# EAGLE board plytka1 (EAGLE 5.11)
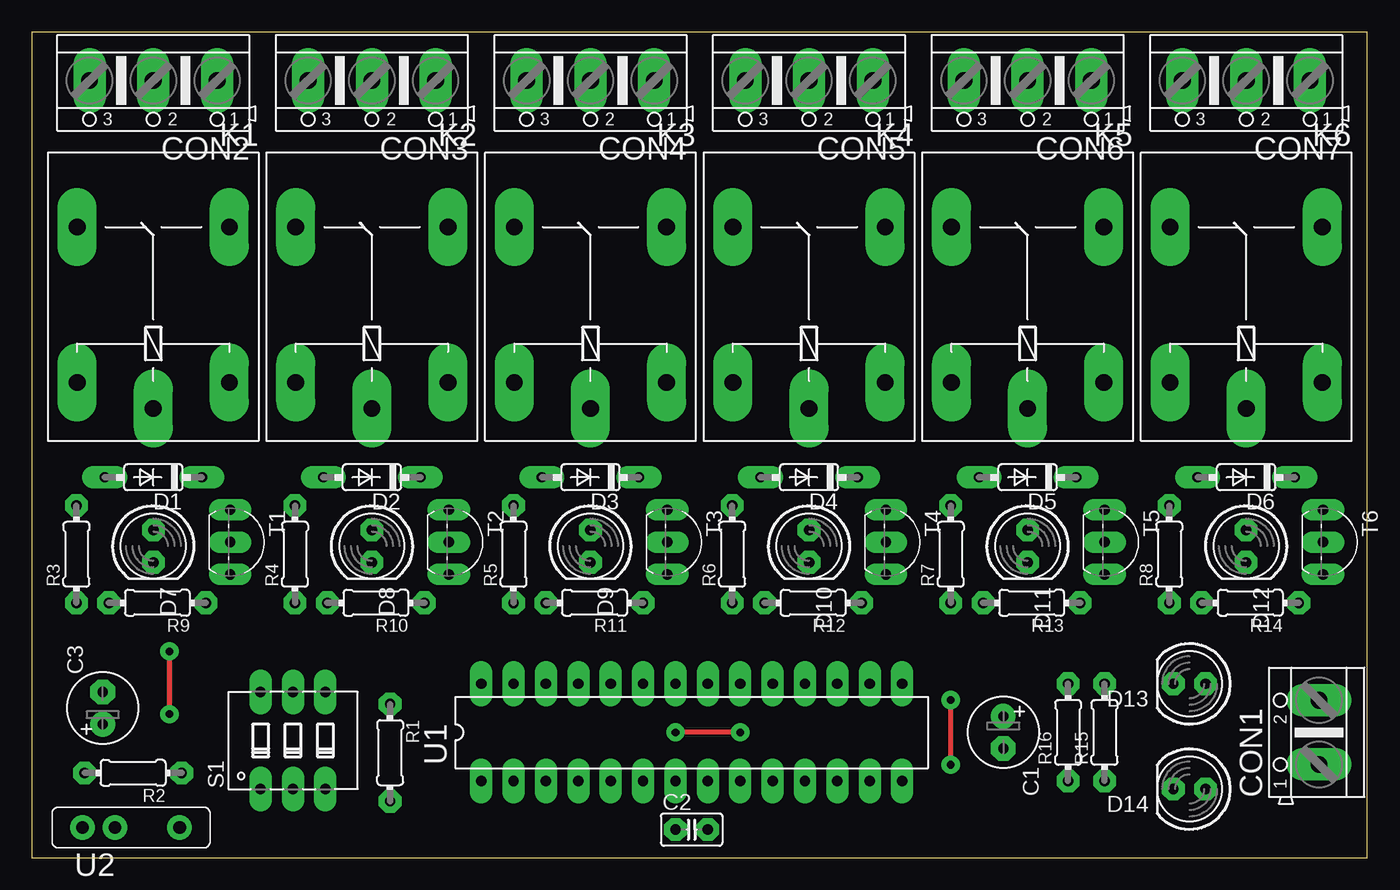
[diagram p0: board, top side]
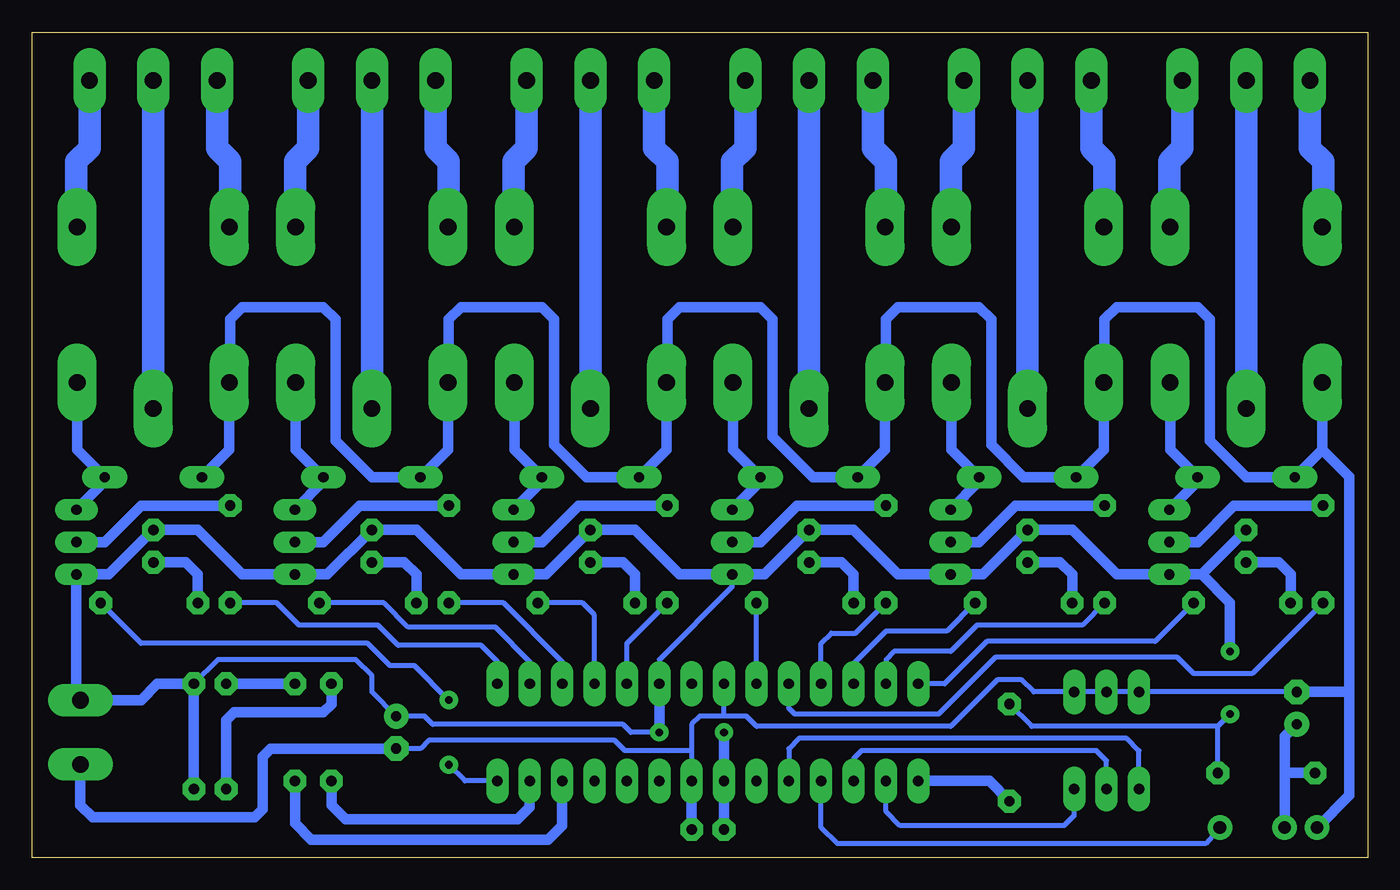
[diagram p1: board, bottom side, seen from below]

Size 104.76 x 64.76 mm. Coordinates in mm from the lower left corner, seen from the top.
Outline: 0,0 104.76,0 104.76,64.76 0,64.76 0,0
Copper layers (1*16): Top 0.035mm / dielectric 1.5mm / Bottom 0.035mm
Design rules "default": minimum track width 10mil, minimum drill 24mil, track to track 8mil, track to pad 8mil, pad to pad 8mil, via to via 8mil, smd to smd 8mil, copper to edge 40mil, drill to drill 8mil, minimum pad ring 10mil, minimum via ring 8mil, stop-mask expansion 4mil, vias tented up to drill 0mil, thermal gap 10mil

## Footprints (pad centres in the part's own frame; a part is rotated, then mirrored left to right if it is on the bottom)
E2,5-6 = drill 0.813 pad 1.93 round: + -1.27,0 | drill 0.813 pad 1.93 octagon: - 1.27,0
C025-025X050 = drill 0.813 pad 1.778 octagon: 1 -1.27,0; 2 1.27,0
AK500/2 = drill 1.321 pad 2.54 long: 1 -2.515,0; 2 2.515,0
AK500/3 = drill 1.321 pad 2.54 long: 1 -5.004,0; 2 0,0; 3 5.004,0
DO35-7 = drill 0.813 pad 1.778 long: A 3.81,0; C -3.81,0
LED5MM = drill 0.813 pad 1.778 octagon: A -1.27,0; K 1.27,0
G5LE = drill 1.321 pad 3.048 long: 1 -7.493,-5.969; 2 -7.493,5.969; O 4.699,5.969; P -9.525,0; S 4.699,-5.969
0204/7 = drill 0.813 pad 1.778 octagon: 1 -3.81,0; 2 3.81,0
DIP03YL = drill 0.813 pad 1.778 long: 1 -2.54,-3.81; 2 0,-3.81; 3 2.54,-3.81; 4 2.54,3.81; 5 0,3.81; 6 -2.54,3.81
TO92-EBC = drill 0.813 pad 1.676 long: B 0,-1.27; C -2.54,-1.27; E 2.54,-1.27
DIL28-3 = drill 0.813 pad 1.778 long: 1 -16.51,-3.81; 2 -13.97,-3.81; 3 -11.43,-3.81; 4 -8.89,-3.81; 5 -6.35,-3.81; 6 -3.81,-3.81; 7 -1.27,-3.81; 8 1.27,-3.81; 9 3.81,-3.81; 10 6.35,-3.81; 11 8.89,-3.81; 12 11.43,-3.81; 13 13.97,-3.81; 14 16.51,-3.81; 15 16.51,3.81; 16 13.97,3.81; 17 11.43,3.81; 18 8.89,3.81; 19 6.35,3.81; 20 3.81,3.81; 21 1.27,3.81; 22 -1.27,3.81; 23 -3.81,3.81; 24 -6.35,3.81; 25 -8.89,3.81; 26 -11.43,3.81; 27 -13.97,3.81; 28 -16.51,3.81
TSOP17_TB1 = drill 1 pad 1.93 round: GND 0,-3.81; VO 0,3.81; VS 0,-1.27

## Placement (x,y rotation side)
C1  10u  [E2,5-6]  76.2,9.84 270 top
C2  100n  [C025-025X050]  51.75,2.22 0 top
C3  4u7  [E2,5-6]  5.56,11.75 90 top
CON1  [AK500/2]  100.97,9.84 90 top
CON2  [AK500/3]  9.53,60.96 180 top
CON3  [AK500/3]  26.67,60.96 180 top
CON4  [AK500/3]  43.81,60.96 180 top
CON5  [AK500/3]  60.96,60.96 180 top
CON6  [AK500/3]  78.11,60.96 180 top
CON7  [AK500/3]  95.25,60.96 180 top
D1  1N4148  [DO35-7]  9.53,29.84 180 top
D2  1N4148  [DO35-7]  26.67,29.84 180 top
D3  1N4148  [DO35-7]  43.81,29.84 180 top
D4  1N4148  [DO35-7]  60.96,29.84 180 top
D5  1N4148  [DO35-7]  78.11,29.84 180 top
D6  1N4148  [DO35-7]  95.25,29.84 180 top
D7  [LED5MM]  9.53,24.45 270 top
D8  [LED5MM]  26.67,24.45 270 top
D9  [LED5MM]  43.81,24.45 270 top
D10  [LED5MM]  60.96,24.45 270 top
D11  [LED5MM]  78.11,24.45 270 top
D12  [LED5MM]  95.25,24.45 270 top
D13  [LED5MM]  90.81,13.65 180 top
D14  [LED5MM]  90.81,5.4 180 top
K1  [G5LE]  9.53,44.77 90 top
K2  [G5LE]  26.67,44.77 90 top
K3  [G5LE]  43.81,44.77 90 top
K4  [G5LE]  60.96,44.77 90 top
K5  [G5LE]  78.11,44.77 90 top
K6  [G5LE]  95.25,44.77 90 top
R1  10k  [0204/7]  28.1,8.25 270 top
R2  220  [0204/7]  7.94,6.67 180 top
R3  3k3  [0204/7]  3.49,23.81 90 top
R4  3k3  [0204/7]  20.64,23.81 90 top
R5  3k3  [0204/7]  37.78,23.81 90 top
R6  3k3  [0204/7]  54.93,23.81 90 top
R7  3k3  [0204/7]  72.07,23.81 90 top
R8  3k3  [0204/7]  89.22,23.81 90 top
R9  150  [0204/7]  9.84,20 180 top
R10  150  [0204/7]  26.99,20 180 top
R11  150  [0204/7]  44.13,20 180 top
R12  150  [0204/7]  61.28,20 180 top
R13  150  [0204/7]  78.42,20 180 top
R14  150  [0204/7]  95.57,20 180 top
R15  150  [0204/7]  84.14,9.84 90 top
R16  150  [0204/7]  81.28,9.84 90 top
S1  [DIP03YL]  20.48,9.21 0 top
T1  BC557  [TO92-EBC]  16.83,24.77 270 top
T2  BC557  [TO92-EBC]  33.97,24.77 270 top
T3  BC557  [TO92-EBC]  51.12,24.77 270 top
T4  BC557  [TO92-EBC]  68.26,24.77 270 top
T5  BC557  [TO92-EBC]  85.41,24.77 270 top
T6  BC557  [TO92-EBC]  102.55,24.77 270 top
U1  ATmega8  [DIL28-3]  51.75,9.84 0 top
U2  TSOP31236  [TSOP17_TB1]  7.78,2.38 270 top

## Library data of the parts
C1-C3 R1-R16 = rcl
CON1-CON7 = con-ptr500
D1-D6 = diode
D7-D14 = led
K1-K6 = relay
S1 = switch-dil
T1-T6 = transistor-pnp
U1 = atmel
U2 = telefunken

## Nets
D1: R9.1 U1.28
D2: R10.1 U1.26
D3: R11.1 U1.23
D4: R12.1 U1.18
D5: R13.1 U1.16
D6: R14.1 U1.14
D7: R15.1 U1.12
D8: R16.1 U1.13
GND: C1.- C2.2 C3.- CON1.1 D1.A D2.A D3.A D4.A D5.A D6.A K1.2 K2.2 K3.2 K4.2 K5.2 K6.2 S1.4 S1.5 S1.6 U1.8 U1.22 U2.GND
IR: U1.4 U2.VO
N$2: CON2.2 K1.P
N$3: CON2.3 K1.O
N$4: CON2.1 K1.S
N$5: D1.C K1.1 T1.C
N$6: C3.+ R2.2 U2.VS
N$7: CON3.3 K2.O
N$8: R3.2 T1.B
N$10: CON3.1 K2.S
N$11: D2.C K2.1 T2.C
N$12: R4.2 T2.B
N$14: CON3.2 K2.P
N$15: CON4.3 K3.O
N$16: CON4.1 K3.S
N$17: D3.C K3.1 T3.C
N$18: R5.2 T3.B
N$20: CON4.2 K3.P
N$21: CON5.3 K4.O
N$22: CON5.1 K4.S
N$23: D4.C K4.1 T4.C
N$24: R6.2 T4.B
N$26: CON5.2 K4.P
N$27: CON6.3 K5.O
N$28: CON6.1 K5.S
N$29: D5.C K5.1 T5.C
N$30: R7.2 T5.B
N$32: CON6.2 K5.P
N$33: CON7.3 K6.O
N$34: CON7.1 K6.S
N$35: D6.C K6.1 T6.C
N$36: R8.2 T6.B
N$38: CON7.2 K6.P
N$39: D7.K R9.2
N$40: D8.K R10.2
N$41: D9.K R11.2
N$42: D10.K R12.2
N$43: D11.K R13.2
N$44: D12.K R14.2
N$45: D13.K R15.2
N$46: D14.K R16.2
N$48: R1.2 U1.1
PR1: R3.1 U1.24
PR2: R4.1 U1.27
PR3: R5.1 U1.25
PR4: R6.1 U1.19
PR5: R7.1 U1.17
PR6: R8.1 U1.15
S1: S1.1 U1.5
S2: S1.2 U1.3
S3: S1.3 U1.2
VCC: C1.+ C2.1 CON1.2 D7.A D8.A D9.A D10.A D11.A D12.A D13.A D14.A R1.1 R2.1 T1.E T2.E T3.E T4.E T5.E T6.E U1.7 U1.20

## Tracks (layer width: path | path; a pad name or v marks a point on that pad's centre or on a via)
D1
  Bottom 0.406: U1.28 33.18,13.65 29.84,16.99 16.67,16.99 R9.1 | U1.28
D2
  Bottom 0.406: R10.1 33.02,17.78 37.78,17.78 40.32,15.24 U1.26
D3
  Bottom 0.406: U1.23 R11.1
D4
  Bottom 0.406: U1.18 60.64,19.05 61.59,20 R12.1
D5
  Bottom 0.406: U1.16 65.72,15.4 68.42,18.1 75.25,18.1 77.15,20 R13.1
D6  (via drill 0.6 pad 1.42)
  Top 0.406: v72.07,7.3 v72.07,12.38
  Bottom 0.406: U1.14 70.8,6.03 v72.07,7.3 | v72.07,12.38 74.77,15.08 76.68,15.08 78.42,16.83 96.2,16.83 R14.1
D7
  Bottom 0.813: U1.12 63.18,2.54 64.29,1.43 82.87,1.43 84.14,2.7 R15.1
D8
  Bottom 0.813: U1.13 65.72,3.97 66.67,3.02 80.17,3.02 81.28,4.13 R16.1
GND
  Bottom 0.406: 53.02,8.41 53.02,10.48 52.38,11.12 50.48,11.12 | 20.64,37.34 K2.2 | 37.78,37.34 K3.2 | 54.93,37.34 K4.2 | 72.07,37.34 K5.2 | 89.22,37.34 K6.2 | 53.02,8.41 58.26,8.41 59.05,9.21 73.66,9.21 74.3,8.57 C1.- | 50.48,11.12 48.74,11.12 47.94,10.32 32.7,10.32 29.05,13.97 27.15,13.97 26.19,13.02 S1.4 | C3.- S1.6 | S1.6 | S1.6 S1.5 S1.4 | S1.4 | 50.48,11.12 U1.22 | 53.02,8.41 U1.8
  Bottom 0.813: K2.2 20.7,32 D2.A 26.99,29.84 29.53,32.38 29.53,42.23 30.48,43.18 36.83,43.18 37.78,42.23 37.78,37.34 | K3.2 37.85,32 D3.A 43.5,29.84 46.67,33.02 46.67,42.23 47.62,43.18 53.98,43.18 54.93,42.23 54.93,37.34 | K4.2 54.99,32 D4.A 61.28,29.84 63.82,32.38 63.82,42.23 64.77,43.18 71.12,43.18 72.07,42.23 72.07,37.34 | K5.2 72.14,32 D5.A 78.11,29.84 80.96,32.7 80.96,42.23 81.92,43.18 88.27,43.18 89.22,42.23 89.22,37.34 | K6.2 89.28,32 D6.A | 20.64,37.34 20.64,42.23 19.68,43.18 13.34,43.18 12.38,42.23 12.38,32.7 9.53,29.84 D1.A 3.56,32 | U2.GND 1.43,4.92 1.43,13.02 | 1.43,13.02 C3.- | 3.56,32 K1.2 | 1.43,13.02 1.43,29.88 3.56,32 | C1.- 86.04,8.57 86.68,7.94 86.68,3.81 87.31,3.17 100.01,3.17 100.97,4.13 CON1.1 | U1.8 C2.2
IR
  Bottom 0.406: U2.VO 12.7,1.11 41.59,1.11 42.86,2.38 U1.4
N$2
  Bottom 1.778: K1.P CON2.2
N$3
  Bottom 1.778: CON2.3 4.52,55.64 3.49,54.61 3.49,49.53 K1.O
N$4
  Bottom 1.778: CON2.1 14.53,55.64 15.56,54.61 15.56,49.53 K1.S
N$5
  Bottom 0.406: 13.34,29.53 D1.C
  Bottom 0.813: K1.1 15.49,32 D1.C | T1.C 13.34,29.53
N$6
  Bottom 0.813: U2.VS 6.51,6.67 | 6.51,6.67 R2.2 | 6.51,6.67 6.51,9.53 C3.+
N$7
  Bottom 1.778: CON3.3 21.67,55.64 20.64,54.61 20.64,49.53 K2.O
N$8
  Bottom 0.813: R3.2 10.48,27.62 13.34,24.77 T1.B
N$10
  Bottom 1.778: CON3.1 31.67,55.64 32.7,54.61 32.7,49.53 K2.S
N$11
  Bottom 0.406: 30.48,29.53 D2.C
  Bottom 0.813: K2.1 32.64,32 D2.C | T2.C 30.48,29.53
N$12
  Bottom 0.813: R4.2 27.62,27.62 30.48,24.77 T2.B
N$14
  Bottom 1.778: K2.P CON3.2
N$15
  Bottom 1.778: CON4.3 38.81,55.64 37.78,54.61 37.78,49.53 K3.O
N$16
  Bottom 1.778: CON4.1 48.82,55.64 49.85,54.61 49.85,49.53 K3.S
N$17
  Bottom 0.406: 47.62,29.53 D3.C
  Bottom 0.813: K3.1 49.78,32 D3.C | T3.C 47.62,29.53
N$18
  Bottom 0.813: R5.2 44.77,27.62 47.62,24.77 T3.B
N$20
  Bottom 1.778: K3.P CON4.2
N$21
  Bottom 1.778: CON5.3 55.96,55.64 54.93,54.61 54.93,49.53 K4.O
N$22
  Bottom 1.778: CON5.1 65.96,55.64 66.99,54.61 66.99,49.53 K4.S
N$23
  Bottom 0.406: 64.77,29.53 D4.C
  Bottom 0.813: K4.1 66.93,32 D4.C | T4.C 64.77,29.53
N$24
  Bottom 0.813: R6.2 61.91,27.62 64.77,24.77 T4.B
N$26
  Bottom 1.778: K4.P CON5.2
N$27
  Bottom 1.778: CON6.3 73.1,55.64 72.07,54.61 72.07,49.53 K5.O
N$28
  Bottom 1.778: CON6.1 83.11,55.64 84.14,54.61 84.14,49.53 K5.S
N$29
  Bottom 0.406: 81.92,29.53 D5.C
  Bottom 0.813: K5.1 84.07,32 D5.C | T5.C 81.92,29.53
N$30
  Bottom 0.813: R7.2 79.06,27.62 81.92,24.77 T5.B
N$32
  Bottom 1.778: K5.P CON6.2
N$33
  Bottom 1.778: CON7.3 90.25,55.64 89.22,54.61 89.22,49.53 K6.O
N$34
  Bottom 1.778: CON7.1 100.25,55.64 101.28,54.61 101.28,49.53 K6.S
N$35
  Bottom 0.406: 99.06,29.53 D6.C
  Bottom 0.813: K6.1 101.22,32 D6.C | T6.C 99.06,29.53
N$36
  Bottom 0.813: R8.2 96.2,27.62 99.06,24.77 T6.B
N$38
  Bottom 1.778: K6.P CON7.2
N$39
  Bottom 0.813: R9.2 6.03,22.23 6.99,23.18 D7.K
N$40
  Bottom 0.813: R10.2 23.18,22.23 24.13,23.18 D8.K
N$41
  Bottom 0.813: R11.2 40.32,22.23 41.27,23.18 D9.K
N$42
  Bottom 0.813: R12.2 57.47,22.23 58.42,23.18 D10.K
N$43
  Bottom 0.813: R13.2 74.61,22.23 75.56,23.18 D11.K
N$44
  Bottom 0.813: R14.2 91.76,22.23 92.71,23.18 D12.K
N$45
  Bottom 0.813: R15.2 D13.K
N$46
  Bottom 0.813: D14.K 89.53,10.79 88.9,11.43 81.92,11.43 81.28,12.06 R16.2
N$48
  Bottom 0.813: U1.1 29.69,6.03 R1.2
PR1
  Bottom 0.406: U1.24 45.4,11.75 44.93,11.27 33.66,11.27 29.21,15.72 14.92,15.72 13.65,14.45 9.05,14.45 R3.1
PR2
  Bottom 0.406: R4.1 22.38,18.26 30.64,18.26 32.7,16.19 37.15,16.19 37.78,15.56 U1.27
PR3
  Bottom 0.406: U1.25 42.86,16.83 42.07,17.62 40.16,17.62 R5.1
PR4
  Bottom 0.406: U1.19 58.1,16.83 R6.1
PR5
  Bottom 0.406: R7.1 67.79,20 63.18,15.4 U1.17
PR6
  Bottom 0.406: R8.1 85.57,20 83.82,18.26 77.63,18.26 76.04,16.67 69.53,16.67 68.26,15.4 U1.15
S1
  Bottom 0.406: U1.5 45.4,8.57 44.61,9.37 18.89,9.37 17.94,8.41 S1.1
S2
  Bottom 0.406: U1.3 40.32,7.78 39.69,8.41 21.27,8.41 20.48,7.62 S1.2
S3
  Bottom 0.406: U1.2 37.78,3.65 36.67,2.54 23.81,2.54 23.02,3.33 S1.3
VCC  (via drill 0.6 pad 1.42)
  Top 0.406: v55.56,9.84 v50.48,9.84 | v10.79,11.27 v10.79,16.19
  Bottom 0.406: T3.E 49.85,21.27 55.56,15.56 U1.20 | 100.94,12.38 CON1.2 | 101.28,12.7 100.97,12.38 | v55.56,9.84 57.78,9.84 58.42,10.48 73.34,10.48 73.98,11.11 C1.+ 78.11,13.02 78.11,14.29 79.38,15.56 90.17,15.56 D13.A | R1.1 26.35,10.32 11.75,10.32 | 11.75,10.32 v10.79,11.27 | R2.1 11.75,10.32 | R2.1
  Bottom 0.813: v50.48,9.84 U1.7 C2.1 | U1.20 v55.56,9.84 | D14.A D13.A 94.93,13.65 96.2,12.38 100.94,12.38 | 101.28,12.7 T6.E 98.74,22.23 D12.A 91.76,25.72 88.27,22.23 T5.E 81.6,22.23 D11.A 74.61,25.72 71.12,22.23 T4.E 64.45,22.23 D10.A 57.47,25.72 53.98,22.23 T3.E 47.31,22.23 D9.A 40.32,25.72 36.83,22.23 T2.E 30.16,22.23 D8.A 23.18,25.72 19.68,22.23 T1.E 13.02,22.23 | 13.02,22.23 D7.A | v10.79,16.19 10.79,20 13.02,22.23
